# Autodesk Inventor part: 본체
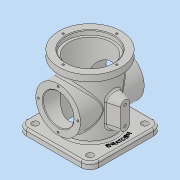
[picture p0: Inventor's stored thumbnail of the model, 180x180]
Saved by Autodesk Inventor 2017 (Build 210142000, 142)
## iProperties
Part Number: 본체
Material: 일반
Document SubType Name: Modeling
Designer: user
Density: 1 g/cm^3
Appearance: 기본값
Author: user
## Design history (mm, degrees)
sketch "스케치1"
  geometry: L1 (57, 57)-(-57, 57); L2 (-57, 57)-(-57, -57); L3 (-57, -57)-(57, -57); L4 (57, -57)-(57, 57); L5 (57, 57)-(-57, -57); L6 (-57, 57)-(57, -57); 1 further point
  constraints: 12 end point, 2 midpoint, 2 parallel, 1 horizontal, 1 perpendicular
  dimensions: "d0" = 114 distance of L3.end L1.start; "d1" = 114 distance of L2.end L3.end
extrude "돌출1" new body sketch "스케치1" distance "d2" = 10; taper "d3" = 0 deg
sketch "스케치2"
  geometry: C1 r 38 at (0, 0); 1 further point
  constraints: 1 centre point, 1 coincident
  dimensions: "d4" = 76 diameter of C1
extrude "돌출2" join sketch "스케치2" distance "d5" = 101; taper "d6" = 0 deg
sketch "스케치3"
  geometry: C1 r 38 at (0, 0) reference; C2 r 49 at (0, 0)
  constraints: 1 centre point, 1 coincident
  dimensions: "d7" = 98 diameter of C2
extrude "돌출3" join sketch "스케치3" distance "d8" = 13; taper "d9" = 0 deg
node "작업 평면1"
sketch "스케치4"
  geometry: L1 (-57, 0)-(57, 0) reference; C1 r 35 at (0, 54); 2 further points
  constraints: 1 centre point, 1 midpoint, 1 vertical alignment
  dimensions: "d29" = 70 diameter of C1; "d30" = 54 distance from line of L1 C1.centre
extrude "돌출4" join sketch "스케치4" distance "d31" = 100; taper "d32" = 0 deg
hole "구멍3" diameter "d35" = 74; stored, may be unused: countersink angle "d39" = 90 deg, drill point angle "d41" = 0 deg; dims "d36" = 6, "d37" = 4, "d38" = 2, "d40" = 7, "d136" = 10, "d137" = 10
hole "구멍4" diameter "d44" = 66; stored, may be unused: countersink angle "d48" = 90 deg, drill point angle "d50" = 118 deg; dims "d42" = 10, "d43" = 10, "d45" = 6, "d46" = 4, "d47" = 2, "d49" = 7
hole "구멍5" diameter "d53" = 48; stored, may be unused: countersink angle "d57" = 90 deg, drill point angle "d59" = 118 deg; dims "d51" = 10, "d52" = 10, "d54" = 6, "d55" = 4, "d56" = 2, "d58" = 7
node "작업 평면2"
sketch "스케치5"
  geometry: L1 (70, 0)-(27, 0); L2 (63, 7)-(34, 7); L3 (34, -7)-(63, -7); L4 (0, 57)-(0, -57) reference; L5 (19, -50)-(89, -50) reference; L6 (0, 0)-(54, 0); A1 r 7 centre (63, 0) between (63, -7) and (63, 7); A2 r 7 centre (34, 0) between (34, 7) and (34, -7); 1 further point
  constraints: 10 end point, 6 point on circle, 4 tangent, 2 centre point, 2 horizontal, 2 point on line, 1 horizontal alignment, 1 midpoint, 1 parallel
  dimensions: "d61" = 7 radius of A1; "d64" = 54 distance of L6.start L6.end; "d67" = 20 distance of A2.centre L6.end; "d68" = 43 distance of L1.end L1.start
extrude "돌출5" join sketch "스케치5" stored distance "d70" = 100; taper "d71" = 0 deg
feature "면 기울기1" dims angle "d72" = 15 deg
sketch "스케치7"
  geometry: C1 r 37 at (0, 0) reference; 1 further point
  constraints: 1 vertical alignment
  dimensions: "d73" = 42 distance of C1.centre point (0, -42)
hole "구멍6" sketch "스케치7" at (0, -42) diameter "d74" = 3.242; stored, may be unused: countersink angle "d78" = 90 deg, drill point angle "d80" = 118 deg; dims "d75" = 6, "d76" = 4, "d77" = 2, "d79" = 8
sketch "스케치8"
  geometry: C1 r 24 at (0, 0) reference; 2 further points
  constraints: 1 vertical alignment
  dimensions: "d84" = 31 distance of C1.centre point (0, 31)
hole "구멍7" sketch "스케치8" at (0, 31) diameter "d85" = 3.242; stored, may be unused: countersink angle "d89" = 90 deg, drill point angle "d91" = 118 deg; dims "d86" = 6, "d87" = 4, "d88" = 2, "d90" = 8
hole "구멍8" diameter "d97" = 4.134; stored, may be unused: countersink angle "d101" = 90 deg, drill point angle "d103" = 118 deg; dims "d95" = 10, "d96" = 10, "d98" = 8, "d99" = 4, "d100" = 2, "d102" = 10
hole "구멍9" diameter "d106" = 4.134; stored, may be unused: countersink angle "d110" = 90 deg, drill point angle "d112" = 118 deg; dims "d104" = 10, "d105" = 10, "d107" = 8, "d108" = 4, "d109" = 2, "d111" = 10
fillet "모깎기1" dims "d113" = 14
hole "구멍10" diameter "d116" = 10; stored, may be unused: countersink angle "d120" = 90 deg, drill point angle "d122" = 118 deg; dims "d114" = 10, "d115" = 10, "d117" = 8, "d118" = 4, "d119" = 2, "d121" = 10
fillet "모깎기2" dims "d123" = 3
chamfer "모따기1" distance "d124" = 1; stored, may be unused: second distance "d125" = 2, angle "d126" = 45 deg
chamfer "모따기2" distance "d127" = 1; stored, may be unused: second distance "d128" = 2, angle "d129" = 45 deg
chamfer "모따기3" distance "d130" = 1; stored, may be unused: second distance "d131" = 2, angle "d132" = 45 deg
sketch "스케치9"
  geometry: C1 r 41 at (0, 0) reference; C2 r 50 at (0, 0)
  constraints: 1 centre point, 1 coincident, 1 other
  dimensions: "d133" = 100 diameter of C2
feature "엠보싱1" sketch "스케치9" dims "d0" = 114, "d1" = 114, "d134" = 0.5, "d135" = 0
node "솔리드1"
pattern_circular "원형 패턴1" dims angle "d82" = 360 deg
pattern_circular "원형 패턴2" dims angle "d93" = 360 deg
mirror "미러1"
mirror "미러2"
mirror "미러3"
other parameters: "d60" = 55
